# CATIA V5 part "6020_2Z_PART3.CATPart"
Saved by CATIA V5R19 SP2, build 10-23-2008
Part number: 6020_2Z_PART3
Bounding box of the stored display mesh (mm): x 1.057 to 1.762, y -68.91 to 68.91, z -68.981 to 68.981
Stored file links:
  G:\EU_thinkMotion\CFAO_2010\MMS_groupe2\MMS_groupe2\OK\nrosalie\nrosalie_cfao_support_d_arme_legere_final\6020_2Z_PART3.CATPart
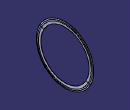
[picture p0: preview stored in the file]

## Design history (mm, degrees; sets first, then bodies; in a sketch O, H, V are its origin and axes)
Set1
  Point1: (0, 0, 0)
  Point2: (1, 0, 0)
  Point3: (0, 1, 0)
  Plane1: type 3Points, Element1 Point1, Element2 Point2, Element3 Point3
Body1 (main body)
  Sketch1 on Plane1, origin (0, 0, 0), H (1, 0, 0), V (0, 1, 0)
    point P1 (1.057, 58)
    point P2 (1.4095, 58)
    line L1 (1.057, 58) -> (1.4095, 58)
    point P3 (1.4095, 58)
    point P4 (1.762, 63.5)
    line L2 (1.4095, 58) -> (1.762, 63.5)
    point P5 (1.762, 63.5)
    point P6 (1.762, 66.2161)
    line L3 (1.762, 63.5) -> (1.762, 66.2161)
    point P7 (1.762, 66.2161)
    point P8 (1.4095, 69)
    line L4 (1.762, 66.2161) -> (1.4095, 69)
    point P9 (1.4095, 69)
    point P10 (1.057, 69)
    line L5 (1.4095, 69) -> (1.057, 69)
    point P11 (1.057, 69)
    point P12 (1.2332, 66.25)
    line L6 (1.057, 69) -> (1.2332, 66.25)
    point P13 (1.2332, 66.25)
    point P14 (1.057, 63.5)
    line L7 (1.2332, 66.25) -> (1.057, 63.5)
    point P15 (1.057, 63.5)
    point P16 (1.057, 58)
    line L8 (1.057, 63.5) -> (1.057, 58)
    point P17 (1.4095, 0)
    point P18 (1.057, 0)
    axis line L9 (1.4095, 0) -> (1.057, 0)
    point P19 (1.057, 58)
    point P20 (1.4095, 58)
    point P21 (1.4095, 58)
    point P22 (1.762, 63.5)
    point P23 (1.762, 63.5)
    point P24 (1.762, 66.2161)
    point P25 (1.762, 66.2161)
    point P26 (1.4095, 69)
    point P27 (1.4095, 69)
    point P28 (1.057, 69)
    point P29 (1.057, 69)
    point P30 (1.2332, 66.25)
    point P31 (1.2332, 66.25)
    point P32 (1.057, 63.5)
    point P33 (1.057, 63.5)
    point P34 (1.057, 58)
    coincidence: P19 P34, P20 P21, P22 P23, P24 P25, P26 P27, P28 P29, P30 P31, P32 P33
  Shaft1: profile Sketch1, axis Sketch1.L9, angle 0, second angle 360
